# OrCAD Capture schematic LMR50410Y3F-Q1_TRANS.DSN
size D; title: LMR50410Y3F-Q1 SIMPLE SWITCHER® 4-V to 36-V, 1-A Buck; rev: 1.0; note: Datasheet: SLUSDW4A      EVM:SLUUC77; note: Synchronous Step Down Converter; note: Converter in SOT-23-6 package
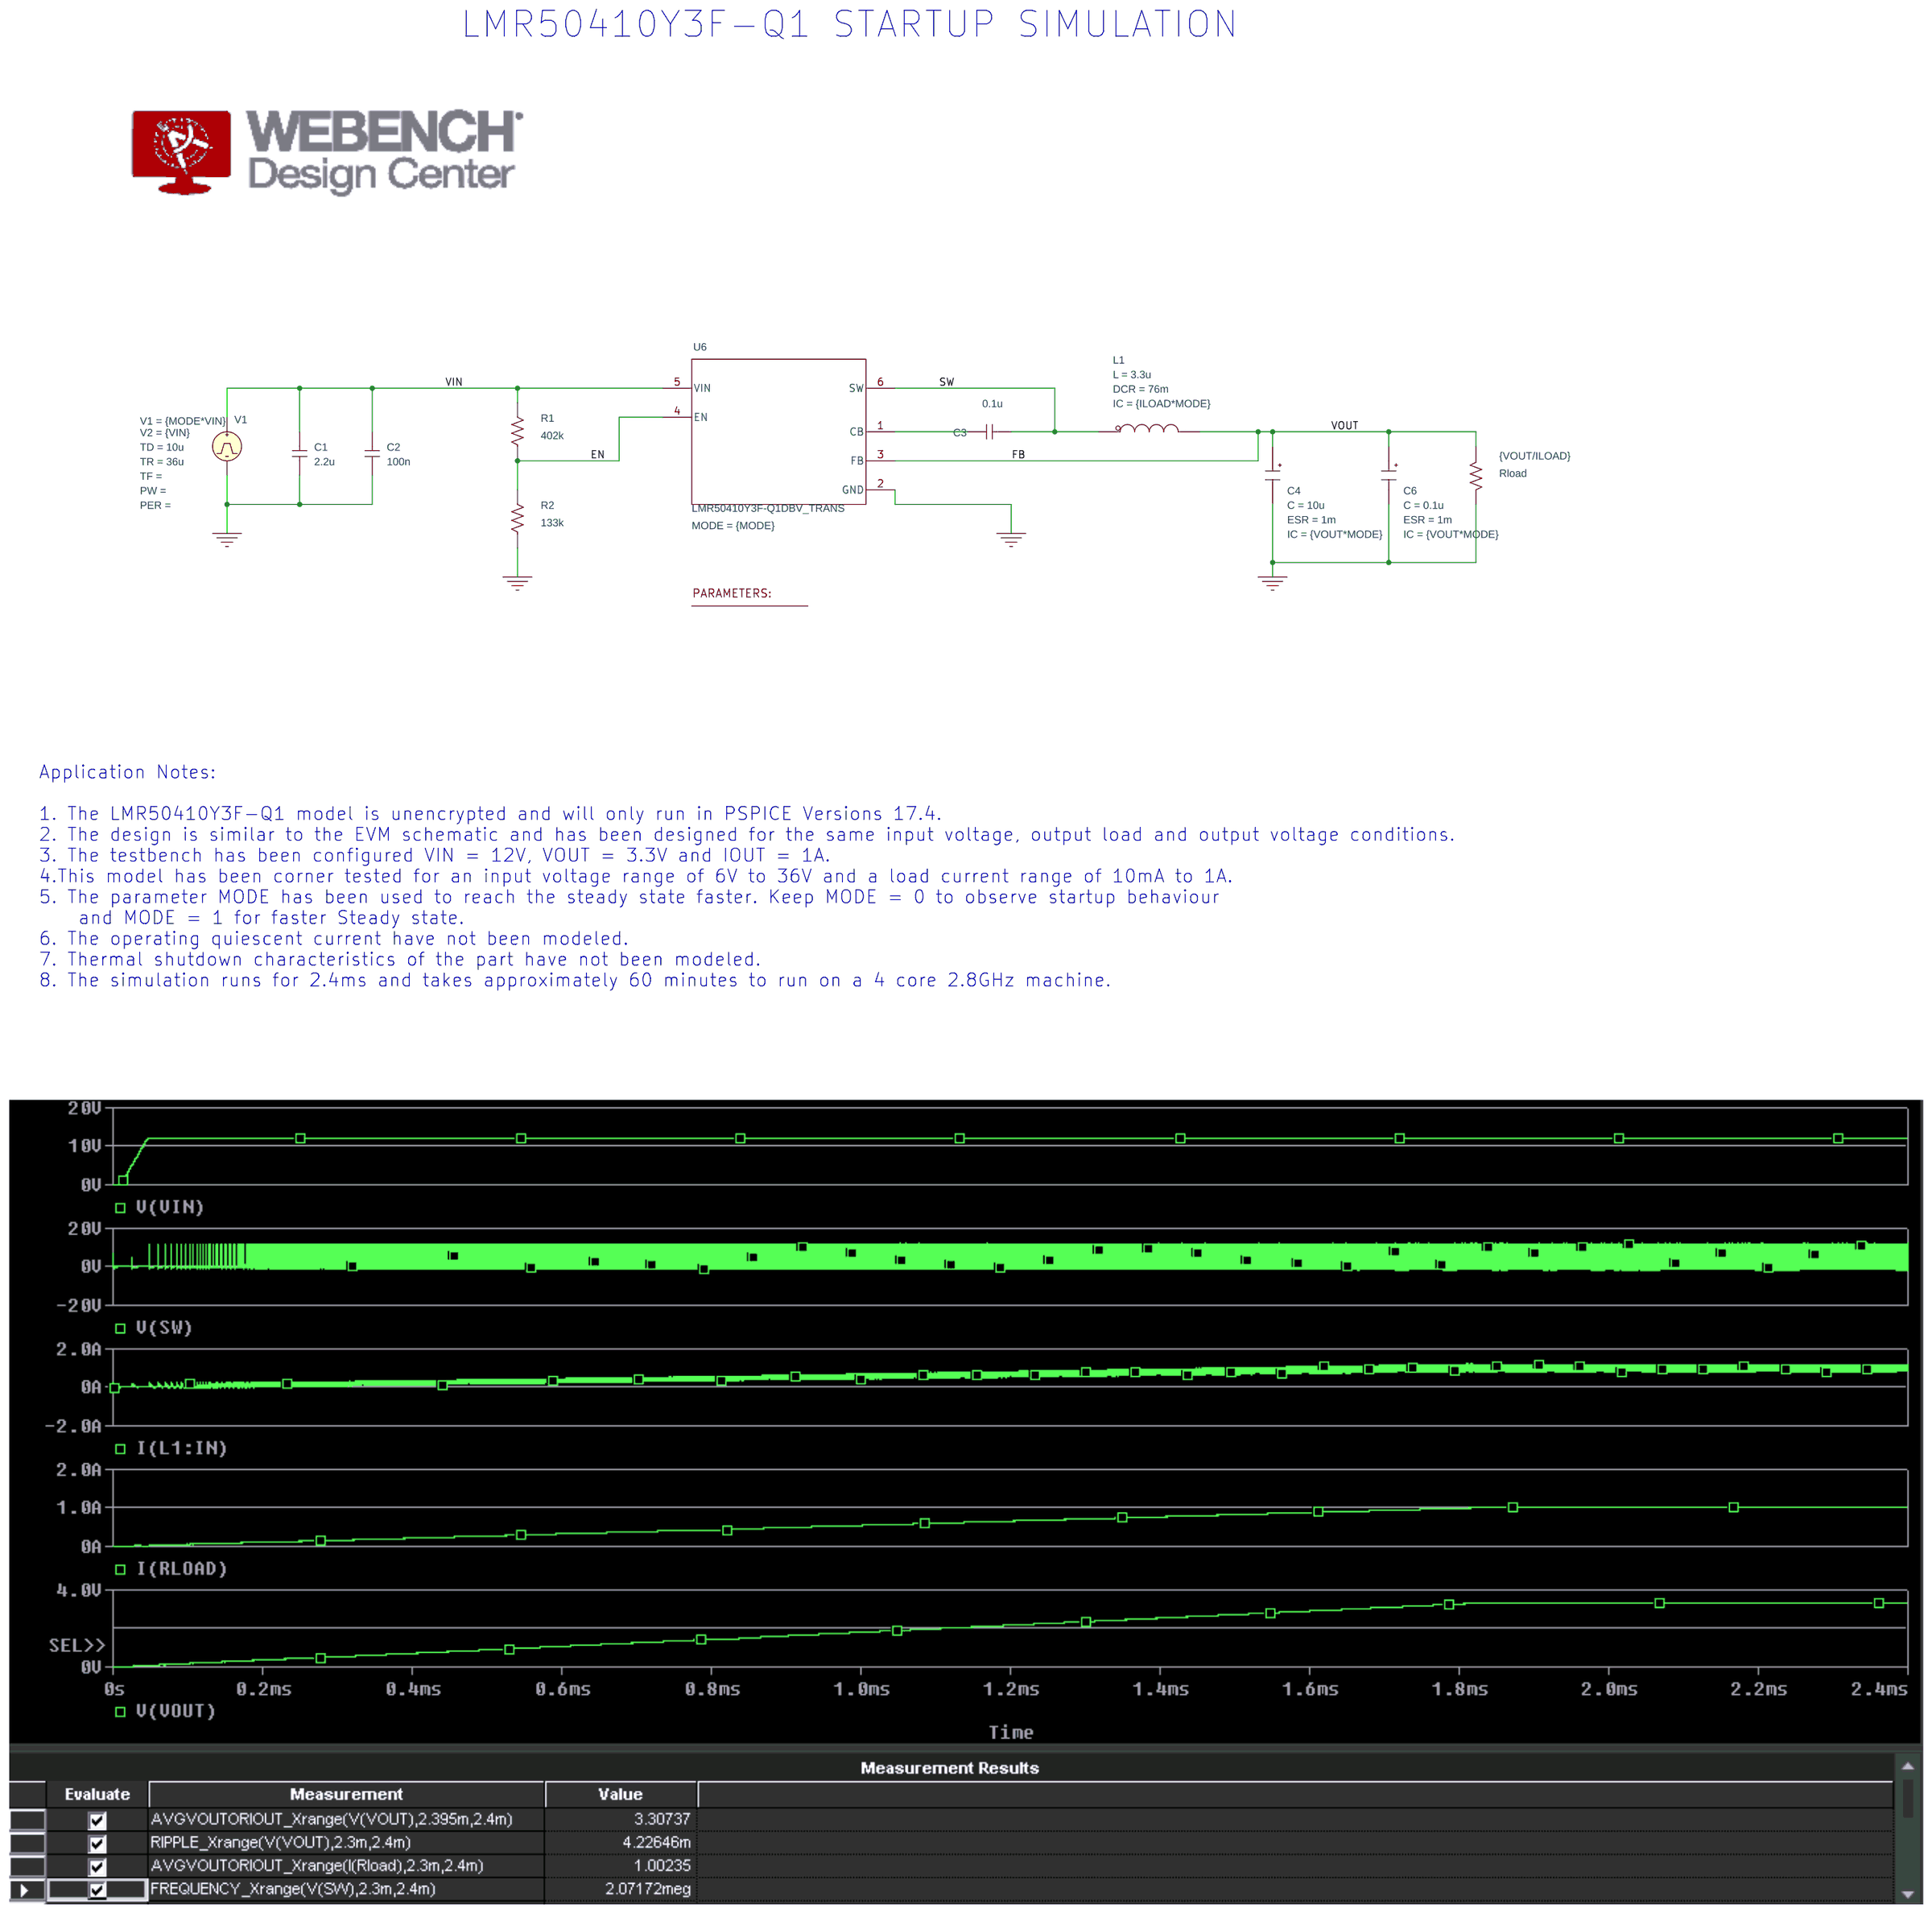
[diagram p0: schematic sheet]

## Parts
1  PARAM
C1  2.2u  [RAD/CK05]
C2  100n  [RAD/CK05]
C3  0.1u  [RAD/CK05]
C4  CESR
C6  CESR
L1  LDCR
R1  402k  [AX/RC05]
R2  133k  [AX/RC05]
Rload  {VOUT/ILOAD}  [AX/RC05]
U6  LMR50410Y3F-Q1DBV_TRANS  [DBV0006A-IPC_A]
V1  VPULSE

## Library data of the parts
1 = PARAM: MODE: 0; VIN: 12; VOUT: 3.3
C1 C2 = C
C3 = C: IC: -3.3
C4 = CESR_0: C: 10u; ESR: 1m; IC: {VOUT*MODE}; PSpiceTemplate: X^@REFDES %IN %OUT @MODEL PARAMS:  ?C|C=@C||C=100u|  ?ESR|ESR=@ESR||ESR=0.01| ?X|X=@X||X=2|  ?IC|IC=@IC||IC=2|; X: 1
C6 = CESR_0: C: 0.1u; ESR: 1m; IC: {VOUT*MODE}; PSpiceTemplate: X^@REFDES %IN %OUT @MODEL PARAMS:  ?C|C=@C||C=100u|  ?ESR|ESR=@ESR||ESR=0.01| ?X|X=@X||X=2|  ?IC|IC=@IC||IC=2|; X: 1
L1 = LDCR_0: DCR: 76m; IC: {ILOAD*MODE}; L: 3.3u; PSpiceTemplate: X^@REFDES %IN %OUT @MODEL PARAMS:  ?L|L=@L||L=1u|  ?DCR|DCR=@DCR||DCR=0.01| ?IC|IC=@IC||IC=0|
R1 R2 Rload = R
U6 = LMR50410Y3F-Q1DBV_TRANS: MODE: {MODE}
V1 = VPULSE: TD: 10u; TR: 36u; V1: {MODE*VIN}; V2: {VIN}

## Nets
VIN: C1.2 C2.2 R1.2 U6.5(VIN) V1.1(+)
0: C1.1 C2.1 C4.3(OUT) C6.3(OUT) R2.1 Rload.2 U6.2(GND) V1.2(-)
EN: R1.1 R2.2 U6.4(EN)
FB: C4.1(IN) C6.1(IN) L1.3(OUT) Rload.1 U6.3(FB)
SW: C3.2 L1.1(IN) U6.6(SW)
N16769650: C3.1 U6.1(CB)

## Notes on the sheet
- LMR50410Y3F-Q1 STARTUP SIMULATION
- Application Notes:
  1. The LMR50410Y3F-Q1 model is unencrypted and will only run in PSPICE Versions 17.4.
  2. The design is similar to the EVM schematic and has been designed for the same input voltage, output load and output voltage conditions.
  3. The testbench has been configured VIN = 12V, VOUT = 3.3V and IOUT = 1A.
  4.This model has been corner tested for an input voltage range of 6V to 36V and a load current range of 10mA to 1A.
  5. The parameter MODE has been used to reach the steady state faster. Keep MODE = 0 to observe startup behaviour
      and MODE = 1 for faster Steady state.
  6. The operating quiescent current have not been modeled.
  7. Thermal shutdown characteristics of the part have not been modeled.
  8. The simulation runs for 2.4ms and takes approximately 60 minutes to run on a 4 core 2.8GHz machine.
